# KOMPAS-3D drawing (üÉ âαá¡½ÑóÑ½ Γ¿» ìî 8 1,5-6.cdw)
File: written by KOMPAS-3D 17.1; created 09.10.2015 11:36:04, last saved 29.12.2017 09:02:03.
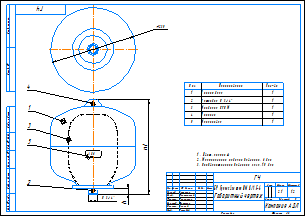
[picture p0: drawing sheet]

Sheet 1: A3, landscape

Title block, sheet 1: name: БР Гранлевел тип НМ 8/1,5-6 / Габаритный чертеж; mass: 2,1; scale: 1:2; sheets: 1; organisation: Компания АДЛ; cell 10: Нач.отд.; sheet format: A3; stored path: \\Fsk1.adlc.lan\files\АП\20_PKO\02_Насосное направление\АУПД\Чертежи на баки\Чертеж.cdw; drawn by: Лощинин; checked by: Хантимеров; technical control: Курлыкина; cell 113: Щетинин; standards control: Долгов; approved by: Рашидов

Views: Вид 1, Спереди, Проекционный вид 2
Referenced files in \\Fsk1\FILES\АП\20_PKO\02_Насосное направление\Разработка\04_Проекты разные\Баки\КД действующая\flexcon r_dwg\Компас\: 8 литров.a3d
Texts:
  ADL
  romans
  romand
  romant
  АДЛ
  Flexcon R8_1.5-6
  TRAZO_Y_PUNTOX2_RGB_0_255_0_SC_2_THICK_0.05
  TRAZO_Y_PUNTOX2_RGB_0_255_0_SC_1_THICK_0.05
  TRAZO_Y_PUNTOX2_RGB_0_255_0_SC_0.3_THICK_0.05
  POLYLINE_STYLE_0.30_RGB_0_0_0
  ACAD_ISO03W100_RGB_223_127_255_SC_0.5_THICK_0.05
  ACAD_ISO03W100_RGB_223_127_255_SC_1_THICK_0.05
  TRAZO_Y_PUNTOX2_RGB_0_255_0_SC_0.25_THICK_0.05
  СONTINUOUS_RGB_223_127_255_THICK_0.05
  ACAD_ISO03W100_RGB_223_127_255_SC_0.25_THICK_0.05
  TRAZO_Y_PUNTOX2_RGB_0_255_0_SC_3_THICK_0.05
  POLYLINE_STYLE_0.35_RGB_0_0_0
  TRAZO_Y_PUNTOX2_RGB_0_255_0_SC_0.5_THICK_0.05
  TRAZO_Y_PUNTOX2_RGB_0_255_0_SC_0.4_THICK_0.05
  ACAD_ISO03W100_RGB_223_127_255_SC_0.046_THICK_0.05
  ACAD_ISO03W100_RGB_223_127_255_SC_0.24_THICK_0.05
  ACAD_ISO03W100_RGB_223_127_255_SC_0.15_THICK_0.05
  ACAD_ISO03W100_RGB_223_127_255_SC_0.0081_THICK_0.05
  ACAD_ISO03W100_RGB_223_127_255_SC_0.0092_THICK_0.05
  ACAD_ISO03W100_RGB_223_127_255_SC_0.14_THICK_0.05
  ACAD_ISO03W100_RGB_223_127_255_SC_0.16_THICK_0.05
  ACAD_ISO03W100_RGB_223_127_255_SC_0.31_THICK_0.05
  ACAD_ISO03W100_RGB_223_127_255_SC_0.47_THICK_0.05
  ACAD_ISO03W100_RGB_223_127_255_SC_0.26_THICK_0.05
  ACAD_ISO03W100_RGB_223_127_255_SC_0.36_THICK_0.05
  CONTINUOUS_RGB_0_0_0_THICK_0.3
  ACAD_ISO03W100_RGB_223_127_255_SC_0.027_THICK_0.05
  ACAD_ISO03W100_RGB_223_127_255_SC_0.18_THICK_0.05
  ACAD_ISO03W100_RGB_223_127_255_SC_0.4_THICK_0.05
  ACAD_ISO03W100_RGB_223_127_255_SC_0.016_THICK_0.05
  ACAD_ISO03W100_RGB_223_127_255_SC_0.057_THICK_0.05
  ACAD_ISO03W100_RGB_223_127_255_SC_0.23_THICK_0.05
  ACAD_ISO03W100_RGB_223_127_255_SC_0.011_THICK_0.05
  ACAD_ISO03W100_RGB_223_127_255_SC_0.42_THICK_0.05
  ACAD_ISO03W100_RGB_223_127_255_SC_0.29_THICK_0.05
  ACAD_ISO03W100_RGB_223_127_255_SC_0.061_THICK_0.05
  ACAD_ISO03W100_RGB_223_127_255_SC_0.32_THICK_0.05
  ACAD_ISO03W100_RGB_223_127_255_SC_0.002_THICK_0.05
  ACAD_ISO03W100_RGB_223_127_255_SC_0.065_THICK_0.05
  ACAD_ISO03W100_RGB_223_127_255_SC_0.28_THICK_0.05
  ACAD_ISO03W100_RGB_223_127_255_SC_0.058_THICK_0.05
  ACAD_ISO03W100_RGB_223_127_255_SC_0.022_THICK_0.05
  ACAD_ISO03W100_RGB_223_127_255_SC_0.0055_THICK_0.05
  ACAD_ISO03W100_RGB_223_127_255_SC_0.19_THICK_0.05
  ACAD_ISO03W100_RGB_223_127_255_SC_0.22_THICK_0.05
  ACAD_ISO03W100_RGB_223_127_255_SC_0.12_THICK_0.05
  ACAD_ISO03W100_RGB_223_127_255_SC_0.21_THICK_0.05
  ACAD_ISO03W100_RGB_223_127_255_SC_0.1_THICK_0.05
  CONTINUOUS_RGB_255_223_127_THICK_0.15
  ACAD_ISO03W100_RGB_223_127_255_SC_0.085_THICK_0.05
  ACAD_ISO03W100_RGB_223_127_255_SC_0.026_THICK_0.05
  ACAD_ISO03W100_RGB_223_127_255_SC_0.05_THICK_0.05
  ACAD_ISO03W100_RGB_223_127_255_SC_0.3_THICK_0.05
  ACAD_ISO03W100_RGB_223_127_255_SC_0.33_THICK_0.05
  ACAD_ISO03W100_RGB_223_127_255_SC_0.49_THICK_0.05
  ACAD_ISO03W100_RGB_223_127_255_SC_0.37_THICK_0.05
  ACAD_ISO03W100_RGB_223_127_255_SC_0.035_THICK_0.05
  ACAD_ISO03W100_RGB_223_127_255_SC_0.018_THICK_0.05
  ACAD_ISO03W100_RGB_223_127_255_SC_0.45_THICK_0.05
  ACAD_ISO03W100_RGB_223_127_255_SC_0.051_THICK_0.05
  CONTINUOUS_RGB_255_0_0_THICK_0.05
  CONTINUOUS_RGB_255_191_0_THICK_0.05
  TRAZO_Y_PUNTOX2_RGB_0_255_0_SC_0.13_THICK_0.05
  CONTINUOUS_RGB_191_255_127_THICK_0.05
  ACAD_ISO03W100_RGB_223_127_255_SC_0.042_THICK_0.05
  ACAD_ISO03W100_RGB_223_127_255_SC_0.27_THICK_0.05
  ACAD_ISO03W100_RGB_223_127_255_SC_0.0016_THICK_0.05
  ACAD_ISO03W100_RGB_223_127_255_SC_0.099_THICK_0.05
  ACAD_ISO03W100_RGB_223_127_255_SC_0.0058_THICK_0.05
  ACAD_ISO03W100_RGB_223_127_255_SC_0.0074_THICK_0.05
  ACAD_ISO03W100_RGB_223_127_255_SC_0.088_THICK_0.05
  ACAD_ISO03W100_RGB_223_127_255_SC_0.0023_THICK_0.05
  ACAD_ISO03W100_RGB_223_127_255_SC_0.38_THICK_0.05
  ACAD_ISO03W100_RGB_223_127_255_SC_0.093_THICK_0.05
  ACAD_ISO03W100_RGB_223_127_255_SC_0.34_THICK_0.05
  ACAD_ISO03W100_RGB_223_127_255_SC_0.087_THICK_0.05
  ACAD_ISO03W100_RGB_223_127_255_SC_0.015_THICK_0.05
  ACAD_ISO03W100_RGB_223_127_255_SC_0.2_THICK_0.05
  ACAD_ISO03W100_RGB_223_127_255_SC_0.41_THICK_0.05
  ACAD_ISO03W100_RGB_223_127_255_SC_0.35_THICK_0.05
  ACAD_ISO03W100_RGB_223_127_255_SC_0.0006_THICK_0.05
  ACAD_ISO03W100_RGB_223_127_255_SC_0.012_THICK_0.05
  CONTINUOUS_RGB_255_223_127_THICK_0.05
  TRAZO_Y_PUNTOX2_RGB_0_255_0_SC_0.35_THICK_0.05
  TRAZO_Y_PUNTOX2_RGB_0_255_0_SC_0.2_THICK_0.05
  TRAZO_Y_PUNTOX2_RGB_0_255_0_SC_0.08_THICK_0.05
  ACAD_ISO03W100_RGB_223_127_255_SC_0.8_THICK_0.05
  TRAZO_Y_PUNTOX2_RGB_0_255_0_SC_0.75_THICK_0.05
  ACAD_ISO03W100_RGB_223_127_255_SC_0.13_THICK_0.05
  ACAD_ISO03W100_RGB_223_127_255_SC_0.063_THICK_0.05
  TRAZO_Y_PUNTOX2_RGB_0_255_0_SC_0.11_THICK_0.05
  HOUND_ISO 0
  HOUND_ISO 1
  ANGLE_ISO 0
  ANGLE_ISO 1
  AR-CONC_ISO
  AR-CONC_ISO 0
  AR-CONC_ISO 1
  AR-CONC_ISO 2
  AR-CONC_ISO 3
  AR-CONC_ISO 4
  AR-CONC_ISO 5
  AR-CONC_ISO 6
  AR-CONC_ISO 7
  AR-CONC_ISO 8
  AR-CONC_ISO 9
  AR-CONC_ISO 10
  AR-CONC_ISO 11
  AR-CONC_ISO 12
  ANSI38_ISO 1
Dimensions and other numbers on the sheet: 261; 16; 25300_Flexcon R8_1.5; 235; 1:2; 1; 2,1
